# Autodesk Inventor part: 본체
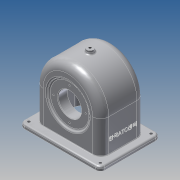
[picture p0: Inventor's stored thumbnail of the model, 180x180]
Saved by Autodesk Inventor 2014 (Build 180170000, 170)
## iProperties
Created: 2016-01
Part Number: 본체
Material: Aluminum 6061
Document SubType Name: Modeling
Designer: user
Density: 2.71 g/cm^3
Appearance: Aluminum - Flat
Mass: 849.26 g
Surface Area: 1020.34 cm^2
Volume: 313.38 cm^3
Author: user
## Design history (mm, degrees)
sketch "Sketch1"
  geometry: L1 (-57, 0)-(57, 0); L2 (57, 0)-(57, -57); L3 (57, -57)-(-57, -57); L4 (-57, -57)-(-57, 0); A1 r 57 centre (0, 0) between (57, 0) and (-57, 0); 2 further points
  constraints: 8 end point, 2 coincident, 2 point on circle, 1 centre point, 1 midpoint
  dimensions: "d1" = 114 distance of L1.start L1.end; "d3" = 57 distance of L1.end L2.end
extrude "Extrusion1" new body sketch "Sketch1" stored distance "d4" = 77; taper "d5" = 0 deg
workplane "Work Plane1"
sketch "Sketch3"
  geometry: L1 (-70, -52)-(70, -52); L2 (70, -52)-(70, 52); L3 (70, 52)-(-70, 52); L4 (-70, 52)-(-70, -52); 3 further points
  constraints: 8 end point, 2 midpoint, 1 horizontal alignment, 1 vertical alignment
  dimensions: "d10" = 140 distance of L2.end L3.end; "d11" = 104 distance of L3.end L1.start
extrude "Extrusion2" join sketch "Sketch3" distance "d12" = 7; taper "d13" = 0 deg
sketch "Sketch4"
  geometry: L1 (70, 64)-(-70, 64) reference; C1 r 31 at (0, 4)
  constraints: 1 centre point
  dimensions: "d113" = 60 distance from line of L1 C1.centre; "d163" = 62 diameter of C1
extrude "Extrusion3" join sketch "Sketch4" distance "d14" = 10; taper "d15" = 0 deg
sketch "Sketch5"
  geometry: L1 (57, 0)-(57, -57) reference; L2 (-57, -57)-(-57, 0) reference; L3 (70, -64)-(-70, -64) reference; L4 (-51, -64)-(-51, 0); L5 (51, 0)-(51, -64); L6 (-51, -64)-(51, -64); A1 r 57 centre (0, 0) between (57, 0) and (-57, 0) reference; A2 r 51 centre (0, 0) between (51, 0) and (-51, 0); 1 further point
  constraints: 6 end point, 2 point on circle, 2 point on line, 1 centre point
  dimensions: "d16" = 6 radial gap between concentric circles of A1 A2
extrude "Extrusion4" cut sketch "Sketch5" stored distance "d17" = 67; taper "d18" = 0 deg
sketch "Sketch6"
  geometry: L1 (-38.5, 0)-(-38.5, -57) reference; L2 (-33.5, 35.747)-(-19.5, 24); L3 (-19.5, 24)-(-19.5, -4); L4 (-33.5, 35.747)-(-33.5, -4); L5 (-38.5, 57)-(-38.5, 0) reference; L6 (-38.5, -4)-(44.143, -4); L7 (33.5, -64)-(-33.5, -64) reference; 1 further point
  constraints: 8 end point, 3 point on line
  dimensions: "d20" = 50 deg angle of L3 L2; "d27" = 5 distance between parallel lines of L5 L4; "d28" = 19 distance between parallel lines of L5 L3; "d114" = 60 distance between parallel lines of L7 L6; "d115" = 56 diameter of L2.end L6
revolve "Revolution1" sketch "Sketch6" stored, may be unused: angle "d29" = 90 deg
fillet "Fillet1" dims "d39" = 9
sketch "Sketch7"
  geometry: L1 (-33.5, 35.747)-(-19.5, 24) reference; L2 (-35.5, 30.899)-(-38.5, 33.416); L3 (-35.5, -4)-(-35.5, 30.899); L4 (-38.5, -4)-(0, -4); L5 (24.5, -64)-(-24.5, -64) reference; L6 (-38.5, 33.416)-(-38.5, -4); 2 further points
  constraints: 8 end point, 1 point on line
  dimensions: "d125" = 60 distance between parallel lines of L5 L4; "d126" = 5 distance between parallel lines of L1 L2; "d127" = 3 distance between parallel lines of L3 L6
revolve "Revolution2" sketch "Sketch7" stored, may be unused: angle "d52" = 90 deg
workplane "Work Plane3"
  workplane "Work Plane2"
sketch "Sketch8"
  geometry: C1 r 6 at (0, 0); 1 further point
  constraints: 1 centre point, 1 coincident
extrude "Extrusion5" join sketch "Sketch8" stored distance "d55" = 67; taper "d56" = 0 deg
fillet "Fillet2" dims "d57" = 3
fillet "Fillet4" dims "d59" = 3
sketch "Sketch9"
  geometry: L1 (-62, 44)-(62, 44); L2 (62, 44)-(62, -44); L3 (62, -44)-(-62, -44); L4 (-62, -44)-(-62, 44); 7 further points
  constraints: 8 end point, 4 coincident, 2 midpoint, 1 horizontal alignment, 1 vertical alignment
  dimensions: "d60" = 88 distance of L3.end L1.start; "d61" = 124 distance of L1.start L1.end
hole "Hole3" sketch "Sketch9" at (-62, -44), (62, -44), (62, 44), (-62, 44) diameter "d62" = 5; stored, may be unused: countersink angle "d66" = 90 deg, drill point angle "d68" = 0 deg; dims "d63" = 6, "d64" = 4, "d65" = 2, "d67" = 16
fillet "Fillet5" dims "d69" = 8
hole "Hole6" diameter "d96" = 4.459; stored, may be unused: countersink angle "d100" = 90 deg, drill point angle "d102" = 0 deg; dims "d97" = 13, "d98" = 4, "d99" = 2, "d101" = 13, "d103" = 10, "d104" = 10
workplane "Work Plane4"
sketch "Sketch12"
  geometry: L1 (-44, -64)-(44, -64) reference; L2 (-38.5, -57)-(-38.5, 0) reference; 4 further points
  constraints: 1 coincident, 1 other
  dimensions: "d106" = 30 distance from line of L1 point (0, -34); "d107" = 38.5 distance from line of L2 point (0, -34)
emboss "Emboss1" sketch "Sketch12" dims "d108" = 0.5, "d109" = 0
fillet "Fillet7" dims "d110" = 14
fillet "Fillet8" dims "d111" = 1
hole "Hole7" diameter "d118" = 40; stored, may be unused: countersink angle "d122" = 90 deg, drill point angle "d124" = 0 deg; dims "d116" = 10, "d117" = 10, "d119" = 12, "d120" = 4, "d121" = 2, "d123" = 15
hole "Hole8" diameter "d130" = 40; stored, may be unused: countersink angle "d134" = 90 deg, drill point angle "d136" = 0 deg; dims "d128" = 10, "d129" = 10, "d131" = 12, "d132" = 4, "d133" = 2, "d135" = 16
fillet "Fillet9" dims "d137" = 3
chamfer "Chamfer2" distance "d138" = 1; stored, may be unused: second distance "d139" = 2, angle "d140" = 45 deg
fillet "Fillet10" dims "d141" = 3
sketch "Sketch13"
  geometry: C1 r 21 at (0, 0) reference; 3 further points
  constraints: 1 coincident, 1 vertical alignment, 2 other
hole "Hole9" sketch "Sketch13" at (0, 28) diameter "d142" = 2.459; stored, may be unused: countersink angle "d146" = 90 deg, drill point angle "d148" = 120 deg; dims "d143" = 7, "d144" = 4, "d145" = 2, "d147" = 9
pattern_circular "Circular Pattern3" dims angle "d150" = 360 deg
sketch "Sketch14" dims "d152" = 48
  geometry: C1 r 21 at (0, 0) reference; 3 further points
  constraints: 1 coincident, 1 vertical alignment, 2 other
hole "Hole10" sketch "Sketch14" at (0, 24) diameter "d153" = 2.459; stored, may be unused: countersink angle "d157" = 90 deg, drill point angle "d159" = 120 deg; dims "d154" = 6, "d155" = 4, "d156" = 2, "d158" = 8
pattern_circular "Circular Pattern4" dims angle "d161" = 360 deg
body "Solid1"
other parameters: "d6" = -64, "d53" = -64, "d54" = 127, "d105" = 123.75
